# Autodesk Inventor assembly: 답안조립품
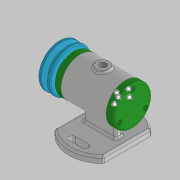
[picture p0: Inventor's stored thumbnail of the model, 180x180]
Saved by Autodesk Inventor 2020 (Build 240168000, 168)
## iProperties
Created: 2021-09
Part Number: 답안조립품
Document SubType Name: Assembly
Designer: Administrator
Author: Administrator
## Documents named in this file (9)
- C:\Users\Administrator\Desktop\710906V1019\답안조립품.iam
- C:\Users\Administrator\Desktop\710906V1019\본체.ipt
- C:\Users\Administrator\Desktop\710906V1019\축.ipt
- C:\Users\Administrator\Desktop\710906V1019\베어링 15x32x9.ipt
- C:\Users\Administrator\Desktop\710906V1019\앞커버.ipt
- C:\Users\Administrator\Desktop\710906V1019\뒤커버.ipt
- C:\Users\Administrator\Desktop\710906V1019\오일 실 15x25x7.ipt
- C:\Users\Administrator\Desktop\710906V1019\키 3x3.ipt
- C:\Users\Administrator\Desktop\710906V1019\V벨트풀리.ipt
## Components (1 placed, 1 different names)
1. V벨트풀리:1
